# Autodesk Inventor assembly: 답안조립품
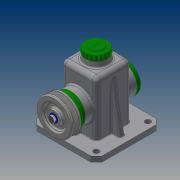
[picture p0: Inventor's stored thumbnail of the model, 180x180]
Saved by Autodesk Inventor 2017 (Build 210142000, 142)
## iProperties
Part Number: 답안조립품
Material: 일반
Document SubType Name: Assembly
Designer: 20
Author: 20
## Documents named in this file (14)
- C:\Users\20\Desktop\470818V1009\답안조립품.iam
- C:\Users\20\Desktop\470818V1009\본체.ipt
- C:\Users\20\Desktop\470818V1009\뒤커버.ipt
- C:\Users\20\Desktop\470818V1009\상부캡.ipt
- C:\Users\20\Desktop\470818V1009\앞커버.ipt
- C:\Users\20\Desktop\470818V1009\베어링 15 x 35 x 11.ipt
- C:\Users\20\Desktop\470818V1009\축.ipt
- C:\Users\20\Desktop\470818V1009\오일실 15 25 7.ipt
- C:\Users\20\Desktop\470818V1009\멈춤링 15 x 1.ipt
- C:\Users\20\Desktop\470818V1009\키 5 x 5 x 14.ipt
- C:\Users\20\Desktop\470818V1009\와셔.ipt
- C:\Users\20\Desktop\470818V1009\V-벨트풀리.ipt
- C:\Users\20\Desktop\470818V1009\볼트 M6 x 12.ipt
- C:\Users\20\Desktop\470818V1009\볼트 M4 x 10.ipt
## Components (1 placed, 1 different names)
1. V-벨트풀리:1
